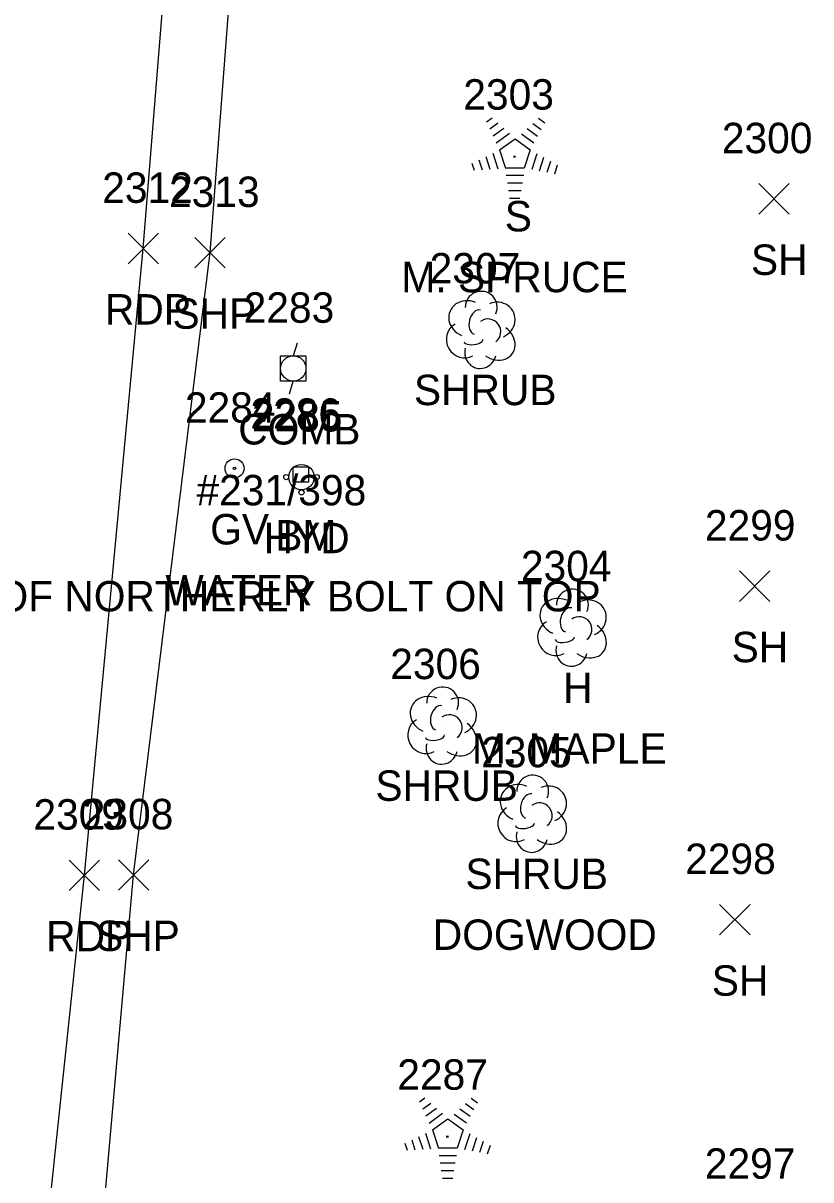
# Model space of a CAD drawing. Extents: x 1653908 to 1654393, y 539913 to 544256.
# Drawn here: x 1654114.5 to 1654166.2, y 542020.2 to 542096.3 of the extents above; entities that cross this region are included whole.
import ezdxf

# ---------------------------------------------------------------- set-up
doc = ezdxf.new("R2010")
doc.units = 0
for name, color, linetype in [('C_A', 7, 'Continuous'), ('C_C', 7, 'Continuous'), ('C_I', 7, 'Continuous'), ('CPBM', 7, 'Continuous'), ('L_A', 7, 'Continuous'), ('L_C', 7, 'Continuous'), ('L_I', 7, 'Continuous'), ('L_TIC', 7, 'Continuous'), ('LSH', 7, 'Continuous'), ('LTC', 7, 'Continuous'), ('LTD', 7, 'Continuous'), ('P_A', 7, 'Continuous'), ('P_I', 7, 'Continuous'), ('P_TIC', 7, 'Continuous'), ('PET', 7, 'Continuous'), ('PSP', 7, 'Continuous'), ('U_A', 7, 'Continuous'), ('U_C', 7, 'Continuous'), ('U_I', 7, 'Continuous'), ('UP', 7, 'Continuous'), ('UWFH', 7, 'Continuous'), ('UWV', 7, 'Continuous')]:
    doc.layers.add(name, color=color, linetype=linetype)

msp = doc.modelspace()

# ---------------------------------------------------------------- linework, layer by layer
at = {"layer": 'CPBM'}
for p, q in [((1654132.22, 542066.103), (1654132.22, 542067.103)), ((1654132.22, 542067.103), (1654133.22, 542067.103)), ((1654133.22, 542067.103), (1654133.22, 542066.103)), ((1654133.22, 542066.103), (1654132.22, 542066.103)), ((1654132.723, 542066.604), (1654132.723, 542066.604)), ((1654132.723, 542066.604), (1654132.723, 542066.604))]:
    msp.add_line(p, q, dxfattribs=at)
at = {"layer": 'L_TIC'}
for points in [[(1654162.791, 542083.72), (1654164.791, 542085.72)], [(1654164.791, 542083.72), (1654162.791, 542085.72)], [(1654161.523, 542058.263), (1654163.523, 542060.263)], [(1654163.523, 542058.263), (1654161.523, 542060.263)], [(1654160.217, 542036.343), (1654162.217, 542038.343)], [(1654162.217, 542036.343), (1654160.217, 542038.343)]]:
    msp.add_lwpolyline(points, dxfattribs=at)
at = {"layer": 'LSH'}
for p, q in [((1654144.518, 542076.16), (1654144.518, 542076.16)), ((1654144.518, 542076.16), (1654144.518, 542076.16)), ((1654141.984, 542050.153), (1654141.984, 542050.153)), ((1654141.984, 542050.153), (1654141.984, 542050.153)), ((1654147.898, 542044.357), (1654147.898, 542044.357)), ((1654147.898, 542044.357), (1654147.898, 542044.357))]:
    msp.add_line(p, q, dxfattribs=at)
for centre in [(1654144.565, 542077.594), (1654142.031, 542051.587), (1654147.945, 542045.791)]:
    msp.add_arc(centre, 1.047, 335.52715, 180.95627, dxfattribs=at)
for centre, major_axis, ratio, start_param, end_param in [((1654143.726, 542076.826), (1.21, -0.512), 0.895232, 1.570796, 4.712389), ((1654145.559, 542076.743), (-1.141, -0.483), 0.949671, 1.570796, 4.712389), ((1654144.309, 542076.618), (-0.208, -0.792), 0.645439, 3.141593, 6.283185), ((1654145.018, 542075.993), (-0.5, 0.667), 0.989748, 3.141593, 6.283185), ((1654143.435, 542075.451), (0.584, -1.042), 0.959034, 3.141593, 6.283185), ((1654145.518, 542075.326), (-1.09, 0.792), 0.841452, 1.570796, 4.712389), ((1654144.06, 542075.41), (-0.625, -0.083), 0.423636, 0, 3.141593), ((1654144.518, 542074.66), (0.265, 1.061), 0.942809, 1.570796, 4.712389), ((1654141.193, 542050.82), (1.21, -0.512), 0.895232, 1.570796, 4.712389), ((1654141.776, 542050.611), (-0.208, -0.792), 0.645439, 3.141593, 6.283185), ((1654143.026, 542050.737), (-1.141, -0.483), 0.949671, 1.570796, 4.712389), ((1654142.484, 542049.987), (-0.5, 0.667), 0.989748, 3.141593, 6.283185), ((1654140.901, 542049.445), (0.584, -1.042), 0.959034, 3.141593, 6.283185), ((1654142.984, 542049.32), (-1.09, 0.792), 0.841452, 1.570796, 4.712389), ((1654141.526, 542049.403), (-0.625, -0.083), 0.423636, 0, 3.141593), ((1654141.985, 542048.653), (0.265, 1.061), 0.942809, 1.570796, 4.712389), ((1654147.106, 542045.023), (1.21, -0.512), 0.895232, 1.570796, 4.712389), ((1654148.94, 542044.94), (-1.141, -0.483), 0.949671, 1.570796, 4.712389), ((1654147.69, 542044.815), (-0.208, -0.792), 0.645439, 3.141593, 6.283185), ((1654146.815, 542043.648), (0.584, -1.042), 0.959034, 3.141593, 6.283185), ((1654148.398, 542044.19), (-0.5, 0.667), 0.989748, 3.141593, 6.283185), ((1654148.898, 542043.523), (-1.09, 0.792), 0.841452, 1.570796, 4.712389), ((1654147.898, 542042.857), (0.265, 1.061), 0.942809, 1.570796, 4.712389), ((1654147.44, 542043.606), (-0.625, -0.083), 0.423636, 0, 3.141593)]:
    msp.add_ellipse(centre, major_axis=major_axis, ratio=ratio, start_param=start_param, end_param=end_param, dxfattribs=at)
at = {"layer": 'LTC'}
for p, q in [((1654144.921, 542089.79), (1654145.275, 542090.047)), ((1654145.13, 542089.324), (1654145.66, 542089.709)), ((1654147.948, 542089.682), (1654148.497, 542089.283)), ((1654148.319, 542090.03), (1654148.738, 542089.726)), ((1654145.34, 542088.859), (1654146.044, 542089.37)), ((1654145.55, 542088.393), (1654146.428, 542089.031)), ((1654147.206, 542088.985), (1654148.015, 542088.396)), ((1654147.577, 542089.334), (1654148.256, 542088.84)), ((1654145.774, 542087.938), (1654146.786, 542088.672)), ((1654145.774, 542087.938), (1654146.161, 542086.744)), ((1654146.786, 542088.672), (1654147.783, 542087.947)), ((1654147.783, 542087.947), (1654147.392, 542086.744)), ((1654144.409, 542087.286), (1654144.62, 542086.634)), ((1654144.864, 542087.502), (1654145.135, 542086.667)), ((1654145.32, 542087.719), (1654145.65, 542086.699)), ((1654148.22, 542087.676), (1654147.882, 542086.637)), ((1654148.665, 542087.426), (1654148.377, 542086.541)), ((1654149.11, 542087.176), (1654148.872, 542086.446)), ((1654143.953, 542087.069), (1654144.105, 542086.601)), ((1654147.392, 542086.744), (1654146.161, 542086.744)), ((1654149.554, 542086.926), (1654149.367, 542086.351)), ((1654147.353, 542086.244), (1654146.209, 542086.244)), ((1654147.27, 542085.744), (1654146.281, 542085.744)), ((1654147.186, 542085.244), (1654146.354, 542085.244)), ((1654147.102, 542084.744), (1654146.427, 542084.744)), ((1654140.512, 542025.374), (1654140.866, 542025.632)), ((1654143.91, 542025.615), (1654144.329, 542025.31)), ((1654140.721, 542024.909), (1654141.25, 542025.293)), ((1654140.931, 542024.443), (1654141.634, 542024.954)), ((1654143.168, 542024.918), (1654143.847, 542024.424)), ((1654143.539, 542025.266), (1654144.088, 542024.867)), ((1654141.14, 542023.977), (1654142.019, 542024.615)), ((1654141.365, 542023.522), (1654142.377, 542024.257)), ((1654142.377, 542024.257), (1654143.374, 542023.532)), ((1654142.797, 542024.57), (1654143.606, 542023.981)), ((1654141.365, 542023.522), (1654141.752, 542022.329)), ((1654143.374, 542023.532), (1654142.982, 542022.329)), ((1654139.544, 542022.653), (1654139.696, 542022.185)), ((1654139.999, 542022.87), (1654140.211, 542022.218)), ((1654140.455, 542023.087), (1654140.726, 542022.251)), ((1654140.91, 542023.303), (1654141.241, 542022.284)), ((1654143.811, 542023.261), (1654143.473, 542022.221)), ((1654144.256, 542023.01), (1654143.968, 542022.126)), ((1654144.7, 542022.76), (1654144.463, 542022.031)), ((1654142.982, 542022.329), (1654141.752, 542022.329)), ((1654142.944, 542021.829), (1654141.799, 542021.829)), ((1654145.144, 542022.51), (1654144.958, 542021.936)), ((1654142.86, 542021.329), (1654141.872, 542021.329)), ((1654142.777, 542020.829), (1654141.945, 542020.829)), ((1654142.693, 542020.329), (1654142.018, 542020.329))]:
    msp.add_line(p, q, dxfattribs=at)
at = {"layer": 'LTD'}
msp.add_line((1654150.51, 542056.588), (1654150.51, 542056.588), dxfattribs=at)
msp.add_line((1654150.51, 542056.588), (1654150.51, 542056.588), dxfattribs=at)
msp.add_arc((1654150.556, 542058.021), 1.047, 335.52715, 180.95627, dxfattribs=at)
for centre, major_axis, ratio, start_param, end_param in [((1654149.718, 542057.254), (1.21, -0.512), 0.895232, 1.570796, 4.712389), ((1654151.551, 542057.171), (-1.141, -0.483), 0.949671, 1.570796, 4.712389), ((1654150.301, 542057.046), (-0.208, -0.792), 0.645439, 3.141593, 6.283185), ((1654149.426, 542055.879), (0.584, -1.042), 0.959034, 3.141593, 6.283185), ((1654151.01, 542056.421), (-0.5, 0.667), 0.989748, 3.141593, 6.283185), ((1654151.51, 542055.754), (-1.09, 0.792), 0.841452, 1.570796, 4.712389), ((1654150.51, 542055.088), (0.265, 1.061), 0.942809, 1.570796, 4.712389), ((1654150.051, 542055.837), (-0.625, -0.083), 0.423636, 0, 3.141593)]:
    msp.add_ellipse(centre, major_axis=major_axis, ratio=ratio, start_param=start_param, end_param=end_param, dxfattribs=at)
at = {"layer": 'P_TIC'}
for points in [[(1654121.37, 542080.456), (1654123.37, 542082.456)], [(1654123.37, 542080.456), (1654121.37, 542082.456)], [(1654125.757, 542080.182), (1654127.757, 542082.182)], [(1654127.757, 542080.182), (1654125.757, 542082.182)], [(1654117.507, 542039.261), (1654119.507, 542041.261)], [(1654119.507, 542039.261), (1654117.507, 542041.261)], [(1654120.735, 542039.282), (1654122.735, 542041.282)], [(1654122.735, 542039.282), (1654120.735, 542041.282)]]:
    msp.add_lwpolyline(points, dxfattribs=at)
at = {"layer": 'PET'}
msp.add_lwpolyline([(1654079.776, 541659.551), (1654080.091, 541663.585), (1654084.434, 541705.035), (1654088.467, 541726.588), (1654090.823, 541750.421), (1654095.245, 541793.922), (1654098.735, 541834.906), (1654102.668, 541873.549), (1654106.19, 541915.359), (1654108.801, 541937.78), (1654112.78, 541976.541), (1654113.712, 541994.764), (1654118.507, 542040.261), (1654122.37, 542081.456), (1654125.512, 542120.567), (1654128.858, 542154.493), (1654132.07, 542197.521), (1654136.387, 542232.744)], dxfattribs=at)
at = {"layer": 'PSP'}
msp.add_lwpolyline([(1654094.458, 541721.214), (1654096.104, 541749.586), (1654101.261, 541800.15), (1654104.956, 541834.324), (1654108.508, 541872.884), (1654110.153, 541890.734), (1654111.767, 541915.009), (1654113.741, 541937.092), (1654116.462, 541969.541), (1654117.65, 541994.217), (1654121.735, 542040.282), (1654126.757, 542081.182), (1654129.731, 542120.034), (1654133.658, 542152.736), (1654138.064, 542196.396), (1654141.276, 542231.97)], dxfattribs=at)
at = {"layer": 'UP'}
for p, q in [((1654132.475, 542075.24), (1654132.225, 542074.407)), ((1654131.392, 542072.74), (1654131.392, 542074.407)), ((1654131.392, 542074.407), (1654133.058, 542074.407)), ((1654133.058, 542074.407), (1654133.058, 542072.74)), ((1654132.225, 542073.574), (1654132.225, 542073.574)), ((1654133.058, 542072.74), (1654131.392, 542072.74)), ((1654131.975, 542071.907), (1654132.225, 542072.74))]:
    msp.add_line(p, q, dxfattribs=at)
msp.add_circle((1654132.225, 542073.574), 0.833, dxfattribs=at)
at = {"layer": 'UWFH'}
msp.add_line((1654132.763, 542066.429), (1654132.763, 542066.429), dxfattribs=at)
for centre, radius in [((1654132.763, 542066.429), 0.833), ((1654131.763, 542066.429), 0.167), ((1654133.763, 542066.429), 0.167), ((1654132.763, 542065.429), 0.167)]:
    msp.add_circle(centre, radius, dxfattribs=at)
at = {"layer": 'UWV'}
for radius in [0.625, 0.0833]:
    msp.add_circle((1654128.367, 542067.005), radius, dxfattribs=at)

# ---------------------------------------------------------------- texts
at = {"layer": 'C_A'}
msp.add_text('BM', height=2, dxfattribs=at).set_placement((1654131.038, 542061.604))
at = {"layer": 'C_C'}
msp.add_text('TOP OF NORTHERLY BOLT ON TOP', height=2, dxfattribs=at).set_placement((1654106.495, 542057.604))
at = {"layer": 'C_I'}
msp.add_text('2286', height=2, dxfattribs=at).set_placement((1654129.408, 542069.604))
at = {"layer": 'L_A'}
for s, p in [('S', (1654146.111, 542082.582)), ('SH', (1654162.279, 542079.72)), ('SHRUB', (1654140.148, 542071.16)), ('SH', (1654161.011, 542054.263)), ('H', (1654149.943, 542051.588)), ('SHRUB', (1654137.614, 542045.153)), ('SHRUB', (1654143.528, 542039.357)), ('SH', (1654159.706, 542032.343))]:
    msp.add_text(s, height=2, dxfattribs=at).set_placement(p)
at = {"layer": 'L_C'}
for s, p in [('M. SPRUCE', (1654139.324, 542078.582)), ('M. MAPLE', (1654143.959, 542047.588)), ('DOGWOOD', (1654141.386, 542035.357))]:
    msp.add_text(s, height=2, dxfattribs=at).set_placement(p)
at = {"layer": 'L_I'}
for s, p in [('2303', (1654143.387, 542090.582)), ('2300', (1654160.366, 542087.72)), ('2307', (1654141.179, 542079.16)), ('2299', (1654159.255, 542062.263)), ('2304', (1654147.171, 542059.588)), ('2306', (1654138.591, 542053.153)), ('2305', (1654144.56, 542047.357)), ('2298', (1654157.958, 542040.343)), ('2287', (1654139.057, 542026.166)), ('2297', (1654159.249, 542020.316))]:
    msp.add_text(s, height=2, dxfattribs=at).set_placement(p)
at = {"layer": 'LTC'}
for p in [(1654146.668, 542087.686), (1654142.259, 542023.27)]:
    msp.add_text('.', height=1.037, rotation=270, dxfattribs=at).set_placement(p)
at = {"layer": 'P_A'}
for s, p in [('RDP', (1654119.858, 542076.456)), ('SHP', (1654124.292, 542076.182)), ('RDP', (1654115.995, 542035.261)), ('SHP', (1654119.271, 542035.282))]:
    msp.add_text(s, height=2, dxfattribs=at).set_placement(p)
at = {"layer": 'P_I'}
for s, p in [('2312', (1654119.677, 542084.456)), ('2313', (1654124.064, 542084.182)), ('2309', (1654115.16, 542043.261)), ('2308', (1654118.397, 542043.282))]:
    msp.add_text(s, height=2, dxfattribs=at).set_placement(p)
at = {"layer": 'U_A'}
for s, p in [('COMB', (1654128.611, 542068.574)), ('GV', (1654126.768, 542062.005)), ('HYD', (1654130.283, 542061.429))]:
    msp.add_text(s, height=2, dxfattribs=at).set_placement(p)
at = {"layer": 'U_C'}
for s, p in [('#231/398', (1654125.863, 542064.574)), ('WATER', (1654123.824, 542058.005))]:
    msp.add_text(s, height=2, dxfattribs=at).set_placement(p)
at = {"layer": 'U_I'}
for s, p in [('2283', (1654128.965, 542076.574)), ('2284', (1654125.107, 542070.005)), ('2285', (1654129.503, 542069.429))]:
    msp.add_text(s, height=2, dxfattribs=at).set_placement(p)

doc.saveas('drawing.dxf')
